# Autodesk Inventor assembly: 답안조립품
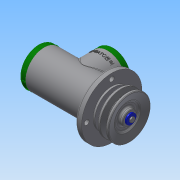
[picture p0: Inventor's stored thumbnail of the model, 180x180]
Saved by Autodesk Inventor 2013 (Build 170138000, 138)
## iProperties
Created: 2016-08
Part Number: 답안조립품
Document SubType Name: Assembly
Designer: Administrator
Author: Administrator
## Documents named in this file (25)
- C:\Users\Administrator\Desktop\460808V1020\답안조립품.iam
- C:\Users\Administrator\Desktop\460808V1020\V-벨트풀리.ipt
- C:\Users\Administrator\Desktop\460808V1020\너트 M10.ipt
- C:\Users\Administrator\Desktop\460808V1020\링크.ipt
- C:\Users\Administrator\Desktop\460808V1020\멈춤링 15 x 1.ipt
- C:\Users\Administrator\Desktop\460808V1020\멈춤링 35x1.6.ipt
- C:\Users\Administrator\Desktop\460808V1020\베어링 15 x 35 x 11.ipt
- C:\Users\Administrator\Desktop\460808V1020\본체.ipt
- C:\Users\Administrator\Desktop\460808V1020\볼트 M4 x 10.ipt
- C:\Users\Administrator\Desktop\460808V1020\볼트 M4 x 12.ipt
- C:\Users\Administrator\Desktop\460808V1020\부시1.ipt
- C:\Users\Administrator\Desktop\460808V1020\부시2.ipt
- C:\Users\Administrator\Desktop\460808V1020\분할핀 1.6 x 12.ipt
- C:\Users\Administrator\Desktop\460808V1020\사이드 커버.ipt
- 사이드 커버.ipt
- C:\Users\Administrator\Desktop\460808V1020\슬라이더.ipt
- C:\Users\Administrator\Desktop\460808V1020\오일 실 15 25 7.ipt
- C:\Users\Administrator\Desktop\460808V1020\와셔 4x16.ipt
- C:\Users\Administrator\Desktop\460808V1020\와셔 10x21.ipt
- C:\Users\Administrator\Desktop\460808V1020\클래스터 핀 6 x 24.ipt
- C:\Users\Administrator\Desktop\460808V1020\키 4 x 4 x 18.ipt
- C:\Users\Administrator\Desktop\460808V1020\탑 부시.ipt
- C:\Users\Administrator\Desktop\460808V1020\탑 커버.ipt
- 탑 커버.ipt
- C:\Users\Administrator\Desktop\460808V1020\편심축.ipt
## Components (10 placed, 3 different names)
1. V-벨트풀리:1
2. ISO 4017 M4 x 10:1
3. ISO 4762 M4 x 12:1
4. ISO 4762 M4 x 12:2
5. ISO 4762 M4 x 12:3
6. ISO 4762 M4 x 12:4
7. ISO 4762 M4 x 12:5
8. ISO 4762 M4 x 12:6
9. ISO 4762 M4 x 12:7
10. ISO 4762 M4 x 12:8
